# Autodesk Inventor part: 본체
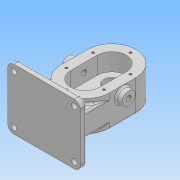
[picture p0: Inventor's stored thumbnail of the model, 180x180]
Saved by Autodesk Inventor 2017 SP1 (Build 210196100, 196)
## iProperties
Part Number: 본체
Material: 일반
Document SubType Name: Modeling
Designer: 00-00
Density: 1 g/cm^3
Appearance: 기본값
Mass: 533.505 g
Surface Area: 785.636 cm^2
Volume: 533.505 cm^3
Author: 00-00
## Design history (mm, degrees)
sketch "스케치1"
  geometry: L1 (-40, 124)-(40, 124); L2 (40, 124)-(40, 0); L3 (40, 0)-(-40, 0); L4 (-40, 0)-(-40, 124); A1 r 40 centre (0, 84) between (40, 84) and (-40, 84); A2 r 40 centre (0, 40) between (-40, 40) and (40, 40); 2 further points
  constraints: 8 end point, 4 point on circle, 4 point on line, 2 centre point, 2 parallel, 2 tangent, 2 vertical alignment, 1 coincident, 1 horizontal, 1 midpoint, 1 perpendicular
  dimensions: "d9" = 80 distance of L2.end L3.end; "d10" = 124 distance of L1.end L2.end; "d11" = 40 radius of A1; "d12" = 40 radius of A2
extrude "돌출1" new body sketch "스케치1" stored distance "d13" = 53; taper "d14" = 0 deg
sketch "스케치2"
  geometry: L1 (0, 84)-(0, 40); L2 (-24, 84)-(-24, 40); L3 (24, 40)-(24, 84); A1 r 24 centre (0, 84) between (24, 84) and (-24, 84); A2 r 24 centre (0, 40) between (-24, 40) and (24, 40); A3 r 40 centre (0, 40) between (-40, 40) and (40, 40) reference; A4 r 40 centre (0, 84) between (40, 84) and (-40, 84) reference; 4 further points
  constraints: 8 end point, 6 point on circle, 4 tangent, 3 vertical alignment, 2 centre point, 1 concentric, 1 midpoint, 1 parallel
  dimensions: "d15" = 24 radius of A1; "d16" = 44 distance of L3.start L3.end
extrude "돌출2" cut sketch "스케치2" distance "d17" = 29; taper "d18" = 0 deg
sketch "스케치3"
  geometry: L1 (24, 40)-(24, 84) reference; L2 (-24, 84)-(-24, 40) reference; C1 r 19 at (0, 84); A1 r 24 centre (0, 40) between (-24, 40) and (24, 40) reference; A2 r 24 centre (0, 84) between (24, 84) and (-24, 84) reference; 1 further point
  constraints: 1 centre point, 1 coincident
  dimensions: "d19" = 19 radius of C1
extrude "돌출3" join sketch "스케치3" distance "d20" = 17; taper "d21" = 0 deg
sketch "스케치5"
  geometry: C1 r 12.5 at (0, 84); C2 r 12.5 at (0, 40); A1 r 24 centre (0, 84) between (24, 84) and (-24, 84) reference; A2 r 24 centre (0, 40) between (-24, 40) and (24, 40) reference; 1 further point
  constraints: 2 centre point, 2 coincident
  dimensions: "d22" = 12.5 radius of C1; "d23" = 12.5 radius of C2
extrude "돌출4" cut sketch "스케치5" distance "d24" = 15; taper "d25" = 0 deg
sketch "스케치6"
  geometry: C1 r 19 at (0, 0) reference; C2 r 8.5 at (0, 0); 1 further point
  constraints: 1 centre point, 1 coincident
  dimensions: "d26" = 8.5 radius of C2
extrude "돌출5" cut sketch "스케치6" stored distance "d27" = 15; taper "d28" = 0 deg
sketch "스케치7"
  geometry: L1 (-24, 40)-(-24, 84) reference; L2 (24, 84)-(24, 40) reference; L3 (0, 84)-(0, 40); L4 (-31, 84)-(-31, 40); L5 (31, 40)-(31, 84); C1 r 12.5 at (0, 84) reference; C2 r 12.5 at (0, 40) reference; A1 r 24 centre (0, 84) between (24, 84) and (-24, 84) reference; A2 r 24 centre (0, 40) between (-24, 40) and (24, 40) reference; A3 r 24 centre (0, 84) between (24, 84) and (-24, 84) reference; A4 r 31 centre (0, 84) between (31, 84) and (-31, 84); A5 r 31 centre (0, 40) between (-31, 40) and (31, 40); 7 further points
  constraints: 8 end point, 5 point on circle, 4 coincident, 4 tangent, 2 centre point, 1 midpoint, 1 parallel, 1 vertical
  dimensions: "d29" = 31 radius of A4
  node "투영된 루프3"
hole "구멍1" sketch "스케치7" diameter "d30" = 4.134; stored, may be unused: countersink angle "d34" = 90 deg, drill point angle "d36" = 118 deg; dims "d31" = 10, "d32" = 4, "d33" = 2, "d35" = 12
sketch "스케치8"
  geometry: C1 r 8.5 at (0, 0) reference; C2 r 19 at (0, 0) reference; C3 r 14 at (0, 0); 1 further point
  constraints: 1 centre point, 1 coincident
  dimensions: "d37" = 14 radius of C3
extrude "돌출6" cut sketch "스케치8" distance "d38" = 7.3; taper "d39" = 0 deg
chamfer "모따기1" distance "d40" = 0.7; stored, may be unused: second distance "d41" = 2, angle "d42" = 30 deg
fillet "모깎기1" dims "d43" = 0.5
chamfer "모따기2" distance "d44" = 1; stored, may be unused: second distance "d45" = 2, angle "d46" = 30 deg
node "작업 평면1"
node "작업 평면2"
sketch "스케치9"
  geometry: L1 (40, 26.5)-(-40, 26.5) reference; L2 (40, -26.5)-(40, 26.5) reference; L3 (-40, 26.5)-(40, 26.5) reference; L4 (-40, -26.5)-(-40, 26.5) reference; L5 (40, -26.5)-(-40, -26.5) reference; L6 (40, -26.5)-(40, 26.5) reference; L7 (-19, -43.5)-(19, -43.5) reference; L8 (60, 56.5)-(-60, 56.5); L9 (-60, 56.5)-(-60, -43.5); L10 (-60, -43.5)-(60, -43.5); L11 (60, -43.5)-(60, 56.5); 2 further points
  constraints: 8 end point, 2 midpoint, 2 parallel, 1 horizontal, 1 perpendicular
  dimensions: "d48" = 120 distance of L10.end L9.end; "d49" = 100 distance of L9.end L8.end
extrude "돌출7" join sketch "스케치9" distance "d50" = 10; taper "d51" = 0 deg
sketch "스케치10"
  geometry: L1 (-40, -18.5)-(40, -18.5); L2 (40, -18.5)-(40, 18.5); L3 (40, 18.5)-(-40, 18.5); L4 (-40, 18.5)-(-40, -18.5); L5 (60, 43.5)-(-60, 43.5) reference; 2 further points
  constraints: 8 end point, 2 parallel, 1 horizontal, 1 midpoint, 1 perpendicular, 1 vertical alignment
  dimensions: "d52" = 80 distance of L3.end L2.end; "d53" = 37 distance of L2.end L1.end; "d54" = 25 distance between parallel lines of L5 L3
extrude "돌출8" join sketch "스케치10" stored distance "d55" = 10; taper "d56" = 0 deg
sketch "스케치11"
  geometry: L1 (53, 84)-(0, 84) reference; L2 (53, -40)-(45, -40) reference; L3 (0, 84)-(0, 44) reference; L4 (53, 44)-(53, 84) reference; L5 (44, 31.5)-(44, 56.5) reference; L6 (53, 44)-(0, 44) reference; L7 (0, 44)-(0, 44) reference; L8 (53, 44)-(0, 44) reference; L9 (53, 44)-(53, 44) reference; L10 (0, 44)-(0, 0) reference; C1 r 11 at (14, 22); 1 further point
  constraints: 1 centre point
  dimensions: "d57" = 11 radius of C1; "d58" = 14 distance from line of C1.centre L10; "d59" = 22 distance from line of C1.centre L6
extrude "돌출9" join sketch "스케치11" distance "d60" = 10; taper "d61" = 0 deg
sketch "스케치13"
  geometry: C1 r 11 at (0, 0) reference; 2 further points
  constraints: 1 coincident
hole "구멍2" sketch "스케치13" at (0, 0) diameter "d62" = 8.376; stored, may be unused: countersink angle "d66" = 90 deg, drill point angle "d68" = 0 deg; dims "d63" = 20, "d64" = 4, "d65" = 2, "d67" = 27.3
sketch "스케치14"
  geometry: L1 (-60, 43.5)-(-60, -56.5) reference; L2 (-60, -56.5)-(60, -56.5) reference; 2 further points
  constraints: 1 other
  dimensions: "d69" = 60 distance from line of point (0, -44.5) L1; "d70" = 12 distance from line of point (0, -44.5) L2
feature "엠보싱1" sketch "스케치14" dims "d9" = 80, "d10" = 124, "d11" = 40, "d12" = 40, "d15" = 24, "d16" = 44, "d71" = 0.5, "d72" = 0
fillet "모깎기2" dims "d73" = 10
sketch "스케치15"
  geometry: L1 (-60, 33.5)-(-60, -46.5) reference; L2 (50, 43.5)-(-50, 43.5) reference; L3 (60, -46.5)-(60, 33.5) reference; L4 (-50, -56.5)-(50, -56.5) reference; A1 r 10 centre (-50, -46.5) between (-60, -46.5) and (-50, -56.5) reference; A2 r 10 centre (-50, 33.5) between (-50, 43.5) and (-60, 33.5) reference; A3 r 10 centre (50, 33.5) between (60, 33.5) and (50, 43.5) reference; A4 r 10 centre (50, -46.5) between (50, -56.5) and (60, -46.5) reference; 5 further points
  constraints: 4 coincident
hole "구멍3" sketch "스케치15" at (-50, 33.5), (50, 33.5), (50, -46.5), (-50, -46.5) diameter "d74" = 9; stored, may be unused: countersink angle "d78" = 90 deg, drill point angle "d80" = 0 deg; dims "d75" = 20, "d76" = 4, "d77" = 2, "d79" = 27.3
fillet "모깎기3" dims "d81" = 3
fillet "모깎기4" dims "d82" = 3
fillet "모깎기5" dims "d83" = 3
fillet "모깎기6" dims "d84" = 3
sketch "스케치16"
  geometry: L1 (-24, 40)-(-24, 84) reference; L2 (24, 84)-(24, 40) reference; L3 (40, 40)-(40, 62) reference; L4 (40, 62)-(40, 84) reference; L5 (-40, 84)-(-40, 62) reference; L6 (-40, 62)-(-40, 40) reference; C1 r 2.067 at (31, 40) reference; C2 r 2.067 at (-31, 84) reference; C3 r 2.067 at (0, 115) reference; C4 r 2.067 at (-31, 40) reference; C5 r 2.067 at (31, 84) reference; A1 r 24 centre (0, 40) between (-24, 40) and (24, 40) reference; A2 r 24 centre (0, 84) between (24, 84) and (-24, 84) reference; A3 r 40 centre (0, 40) between (-40, 40) and (40, 40) reference; A4 r 40 centre (0, 84) between (40, 84) and (-40, 84) reference; 2 further points
  constraints: 1 vertical alignment
  dimensions: "d86" = 106 distance of C3.centre point (0, 9)
hole "구멍4" sketch "스케치16" at (0, 9) diameter "d87" = 4.134; stored, may be unused: countersink angle "d91" = 90 deg, drill point angle "d93" = 118 deg; dims "d88" = 10, "d89" = 4, "d90" = 2, "d92" = 12
fillet "모깎기7" dims "d94" = 3
node "솔리드1"
mirror "미러1"
node "투영된 루프1"
node "투영된 루프2"
node "투영된 루프4"
node "투영된 루프5"
node "투영된 루프6"
node "투영된 루프8"
node "투영된 루프9"
other parameters: "d47" = -28
